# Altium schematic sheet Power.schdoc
size 414 x 194 mm
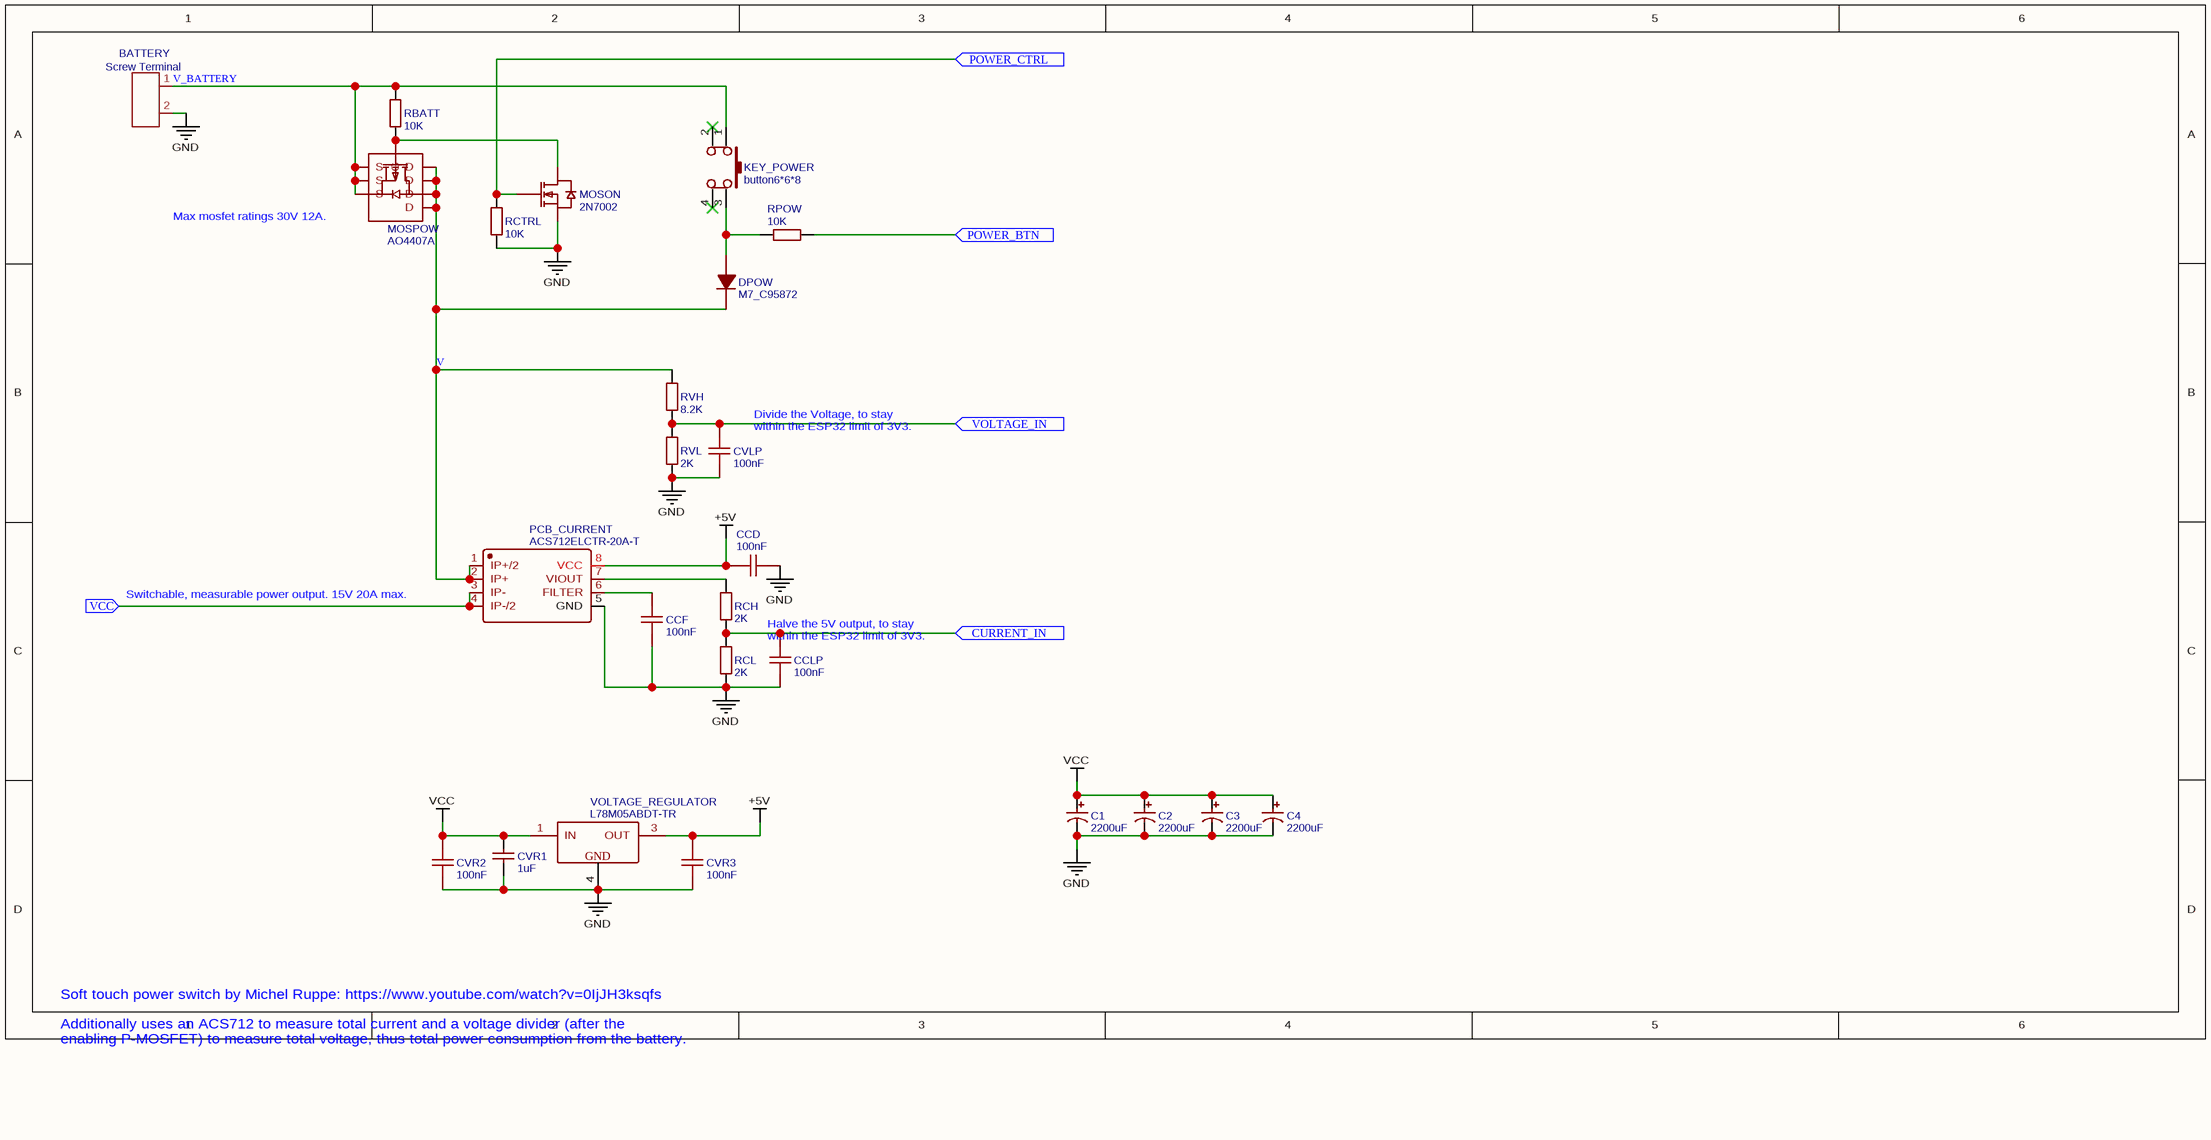
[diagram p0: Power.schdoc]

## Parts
BATTERY  Screw Terminal  [H2-5.0-10.5X8.0MM]
C1  2200uF  [SIDECAP_13X21]
C2  2200uF  [SIDECAP_13X21]
C3  2200uF  [SIDECAP_13X21]
C4  2200uF  [SIDECAP_13X21]
CCD  100nF  [0603]
CCF  100nF  [0603]
CCLP  100nF  [0603]
CVLP  100nF  [0603]
CVR1  1uF  [0603]
CVR2  100nF  [0603]
CVR3  100nF  [0603]
DPOW  M7_C95872  [DO-214AC_L4.3-W2.7-LS5.3-RD]
KEY_POWER  button6*6*8  [KEY-6.0*6.0-2]
MOSON  2N7002  [SOT-23-DOT-TOP-LEFT]
MOSPOW  AO4407A  [SOIC-8-DOT-BOT-LEFT]
PCB_CURRENT  ACS712ELCTR-20A-T  [SOIC-8-DOT-BOT-LEFT]
RBATT  10K  [0603]
RCH  2K  [0603]
RCL  2K  [0603]
RCTRL  10K  [0603]
RPOW  10K  [0603]
RVH  8.2K  [0603]
RVL  2K  [0603]
VOLTAGE_REGULATOR  L78M05ABDT-TR  [TO-252-2-DOT-TOP-LEFT]

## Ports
CURRENT_IN, POWER_BTN, POWER_CTRL, VCC, VOLTAGE_IN

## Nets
+5V: CCD.2 CVR3.2 PCB_CURRENT.8(VCC) VOLTAGE_REGULATOR.3(OUT)
GND: BATTERY.2 C1.2 C2.2 C3.2 C4.2 CCD.1 CCF.1 CCLP.1 CVLP.1 CVR1.1 CVR2.1 CVR3.1 MOSON.2(S) PCB_CURRENT.5(GND) RCL.1 RCTRL.1 RVL.1 VOLTAGE_REGULATOR.4(GND)
VCC: C1.1 C2.1 C3.1 C4.1 CVR1.2 CVR2.2 VOLTAGE_REGULATOR.1(IN)
CURRENT_IN: CCLP.2 RCH.1 RCL.2 ; port CURRENT_IN
POWER_BTN: RPOW.1 ; port POWER_BTN
POWER_CTRL: MOSON.1(G) RCTRL.2 ; port POWER_CTRL
V: DPOW.1(K) MOSPOW.5(D) MOSPOW.6(D) MOSPOW.7(D) MOSPOW.8(D) PCB_CURRENT.1(IP+/2) PCB_CURRENT.2(IP+) RVH.2
V_BATTERY: BATTERY.1 KEY_POWER.1 MOSPOW.1(S) MOSPOW.2(S) MOSPOW.3(S) RBATT.2
VCC: PCB_CURRENT.3(IP-) PCB_CURRENT.4(IP-/2) ; port VCC  [a separate net that carries the same name]
VOLTAGE_IN: CVLP.2 RVH.1 RVL.2 ; port VOLTAGE_IN
NetCCF_2: CCF.2 PCB_CURRENT.6(FILTER)
NetDPOW_2: DPOW.2(A) KEY_POWER.3 RPOW.2
NetMOSON_3: MOSON.3(D) MOSPOW.4(G) RBATT.1
NetPCB_CURRENT_7: PCB_CURRENT.7(VIOUT) RCH.2

Not connected (* = marked no-connect by the designer): KEY_POWER 2* 4*

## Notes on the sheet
- (near MOSPOW) Max mosfet ratings 30V 12A.
- Divide the Voltage, to stay
  within the ESP32 limit of 3V3.
- Switchable, measurable power output. 15V 20A max.
- (near CCLP) Halve the 5V output, to stay
  within the ESP32 limit of 3V3.
- Soft touch power switch by Michel Ruppe: https://www.youtube.com/watch?v=0IjJH3ksqfs
  Additionally uses an ACS712 to measure total current and a voltage divider (after the
  enabling P-MOSFET) to measure total voltage, thus total power consumption from the battery.

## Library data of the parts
C1-C4 = 2200uF: BOM_Manufacturer: ValuePro; BOM_Manufacturer Part: 2200uF 25V 13*20; nameAlias: Capacitance
CCD CCF CCLP CVLP CVR2 CVR3 = 100nF: BOM_Manufacturer: YAGEO; BOM_Manufacturer Part: CC0603KRX7R9BB104; nameAlias: Capacitance; SMT Type: Basic
CVR1 = 1uF: BOM_Manufacturer Part: CL10A105KB8NNNC; BOM_Manufacturer: SAMSUNG; nameAlias: Capacitance; SMT Type: Basic
DPOW = M7_C95872: BOM_Manufacturer: MDD; BOM_Manufacturer Part: M7; SMT Type: Basic
KEY_POWER = button6*6*8: BOM_Manufacturer: ReliaPro
MOSON = 2N7002: BOM_Manufacturer: CJ; SMT Type: Basic
MOSPOW = AO4407A: BOM_Manufacturer: AOS; SMT Type: Basic
PCB_CURRENT = ACS712ELCTR-20A-T: BOM_Manufacturer: ALLEGRO; SMT Type: Basic
RBATT RCTRL RPOW = 10K: BOM_Manufacturer: UniOhm; BOM_Manufacturer Part: 0603WAF1002T5E; nameAlias: Resistance (Ohms); SMT Type: Basic
RCH RCL RVL = 2K: BOM_Manufacturer: UniOhm; BOM_Manufacturer Part: 0603WAF2001T5E; nameAlias: Resistance (Ohms); SMT Type: Basic
RVH = 8.2K: BOM_Manufacturer: UniOhm; BOM_Manufacturer Part: 0603WAF8201T5E; nameAlias: Resistance (Ohms); SMT Type: Basic
VOLTAGE_REGULATOR = L78M05ABDT-TR: BOM_Manufacturer: STMicroelectronics; SMT Type: Basic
